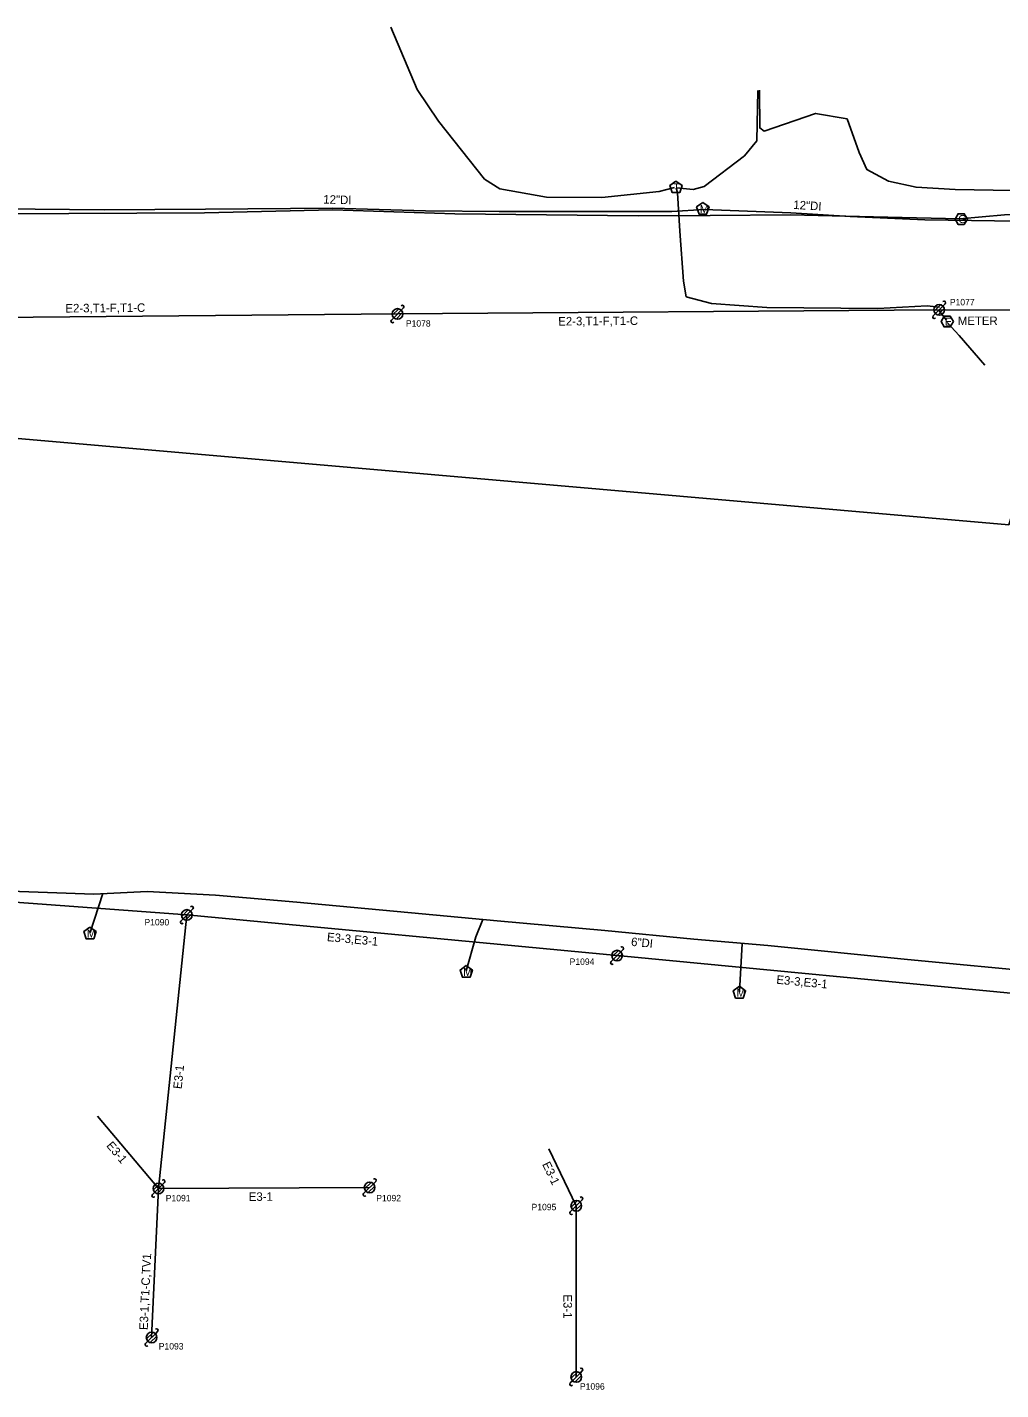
# Model space of a CAD drawing. Extents: x 1614474 to 1865144, y 1098877 to 1212550.
# Drawn here: x 1801312 to 1801769, y 1187738 to 1188377 of the extents above; entities that cross this region are included whole.
import ezdxf

# ---------------------------------------------------------------- set-up
doc = ezdxf.new("R2010")
doc.units = 0
for name, color, linetype in [('BFUSER_FIBERSPAN', 7, 'Continuous'), ('RD_EX_SU_Elec', 7, 'Continuous'), ('RD_EX_SU_Gas', 7, 'Continuous'), ('RD_EX_SU_H2O', 7, 'Continuous'), ('RD_EX_SU_Ovhd', 7, 'Continuous'), ('RD_EX_SU_Pole', 7, 'Continuous'), ('RD_EX_SU_Telecom', 7, 'Continuous'), ('RD_EX_SU_TX_Elec', 7, 'Continuous'), ('RD_EX_SU_TX_H2O', 7, 'Continuous'), ('RD_EX_SU_TX_Pole', 7, 'Continuous')]:
    doc.layers.add(name, color=color, linetype=linetype)

# ---------------------------------------------------------------- blocks, each defined once
blk = doc.blocks.new('SUE_GVC')
at = {"layer": 'RD_EX_SU_Gas'}
blk.add_lwpolyline([(1.44, -2.5), (2.89, 0), (1.44, 2.5), (-1.44, 2.5), (-2.89, 0), (-1.44, -2.5)], close=True, dxfattribs=at)
blk.add_text('G', height=3.75, dxfattribs=at).set_placement((-1.34, -1.88))
blk = doc.blocks.new('SUE_TPP')
at = {"layer": 'RD_EX_SU_Telecom'}
blk.add_lwpolyline([(0, 3), (-2.85, 0.93), (-1.76, -2.43), (1.76, -2.43), (2.85, 0.93)], close=True, dxfattribs=at)
blk.add_text('T', height=3.75, dxfattribs=at).set_placement((-1.25, -1.88))
blk = doc.blocks.new('SUE_WM')
at = {"layer": 'RD_EX_SU_H2O'}
blk.add_lwpolyline([(0, 3.05), (-2.9, 0.94), (-1.79, -2.47), (1.79, -2.47), (2.9, 0.94)], close=True, dxfattribs=at)
blk.add_text('M', height=3.75, dxfattribs=at).set_placement((-1.43, -1.88))
blk = doc.blocks.new('SUE_PP')
at = {"layer": 'RD_EX_SU_Pole'}
for p, q in [((-2.41, -0.65), (0.65, 2.41)), ((-1.77, -1.77), (1.77, 1.77)), ((-0.65, -2.41), (2.41, 0.65)), ((1.77, 1.77), (2.83, 2.83)), ((-2.83, -2.83), (-1.77, -1.77))]:
    blk.add_line(p, q, dxfattribs=at)
blk.add_circle((0, 0), 2.5, dxfattribs=at)
for centre, start, end in [((2.3, 3.36), 315, 135), ((-2.3, -3.36), 135, 315)]:
    blk.add_arc(centre, 0.75, start, end, dxfattribs=at)

msp = doc.modelspace()

# ---------------------------------------------------------------- linework, layer by layer
at = {"layer": 'BFUSER_FIBERSPAN'}
msp.add_lwpolyline([(1800084.25, 1188303.4), (1800779.19, 1188255.87), (1800833.78, 1188281.15), (1801076.57, 1188204.5), (1801772.73, 1188143.98), (1801793.73, 1188209.4), (1801787.99, 1188210.07)], dxfattribs=at)
at = {"layer": 'RD_EX_SU_Elec'}
msp.add_line((1801740.16, 1188244.25), (1801743.54, 1188239.79), dxfattribs=at)
msp.add_lwpolyline([(1801746.74, 1188239.17), (1801745.3, 1188241.67), (1801742.41, 1188241.67), (1801740.97, 1188239.17), (1801742.41, 1188236.67), (1801745.3, 1188236.67)], close=True, dxfattribs=at)
msp.add_lwpolyline([(1801743.9, 1188238.76), (1801749.5, 1188232.67), (1801761.56, 1188218.75)], dxfattribs=at)
at = {"layer": 'RD_EX_SU_Gas'}
msp.add_lwpolyline([(1801300.18, 1188289.75), (1801395.65, 1188290.16), (1801455.8, 1188291.53), (1801513.04, 1188289.66), (1801598.92, 1188288.81), (1801632.69, 1188288.87), (1801670.37, 1188289.16), (1801709.24, 1188288.32), (1801749.77, 1188287.36), (1801770.8, 1188289.23), (1801835.8, 1188289.57), (1801882.8, 1188288.37), (1801925.16, 1188284.33), (1801950.2, 1188282.64), (1801971.28, 1188282.21), (1801996.82, 1188281.83), (1802039.19, 1188282.29), (1802043.42, 1188284.85)], dxfattribs=at)
at = {"layer": 'RD_EX_SU_H2O'}
for p, q in [((1801341.96, 1187952.76), (1801347.89, 1187971.05)), ((1801646.47, 1187925.03), (1801647.68, 1187947.69))]:
    msp.add_line(p, q, dxfattribs=at)
for points in [[(1801299.98, 1188292.06), (1801348.52, 1188291.53), (1801396.06, 1188291.83), (1801455.82, 1188292.39), (1801499.16, 1188291.09), (1801533.71, 1188290.84), (1801614.7, 1188290.73), (1801629.95, 1188291.7), (1801670.47, 1188290.08), (1801698.41, 1188288.36), (1801733.35, 1188286.84), (1801787.88, 1188286.07), (1801857.46, 1188285.91)], [(1801295.73, 1187972.44), (1801343.67, 1187970.84), (1801368.71, 1187972.11), (1801400.74, 1187970.36), (1801438.8, 1187967.03), (1801497.7, 1187961.57), (1801532.75, 1187958.36), (1801583.27, 1187953.8), (1801624.99, 1187949.77), (1801659.67, 1187946.69), (1801725.3, 1187940.21), (1801791.08, 1187933.95)], [(1801518.36, 1187934.84), (1801522.8, 1187950.84), (1801526.05, 1187958.97)]]:
    msp.add_lwpolyline(points, dxfattribs=at)
at = {"layer": 'RD_EX_SU_Ovhd'}
for p, q in [((1801236.17, 1188240.62), (1801486.07, 1188242.75)), ((1801486.07, 1188242.75), (1801740.09, 1188244.68)), ((1801740.09, 1188244.68), (1801966.65, 1188244.29)), ((1801180.44, 1187976.55), (1801387.3, 1187961.03)), ((1801374.01, 1187832.8), (1801387.3, 1187961.03)), ((1801387.3, 1187961.03), (1801589.05, 1187942)), ((1801589.05, 1187942), (1801781.89, 1187923.55)), ((1801345.46, 1187866.75), (1801374.01, 1187832.8)), ((1801557, 1187851.42), (1801569.91, 1187824.74)), ((1801370.78, 1187762.99), (1801374.01, 1187832.8)), ((1801374.01, 1187832.8), (1801473.03, 1187833.3)), ((1801569.92, 1187744.5), (1801569.91, 1187824.74))]:
    msp.add_line(p, q, dxfattribs=at)
at = {"layer": 'RD_EX_SU_Pole'}
for p, q in [((1801737.67, 1188244.03), (1801740.73, 1188247.09)), ((1801738.32, 1188242.91), (1801741.85, 1188246.45)), ((1801741.85, 1188246.45), (1801742.92, 1188247.51)), ((1801483.24, 1188239.92), (1801484.3, 1188240.98)), ((1801483.66, 1188242.11), (1801486.72, 1188245.17)), ((1801484.3, 1188240.98), (1801487.84, 1188244.52)), ((1801485.42, 1188240.34), (1801488.49, 1188243.4)), ((1801487.84, 1188244.52), (1801488.9, 1188245.58)), ((1801737.26, 1188241.85), (1801738.32, 1188242.91)), ((1801739.44, 1188242.26), (1801742.5, 1188245.32)), ((1801384.47, 1187958.2), (1801385.53, 1187959.26)), ((1801384.89, 1187960.38), (1801387.95, 1187963.44)), ((1801385.53, 1187959.26), (1801389.07, 1187962.79)), ((1801386.66, 1187958.61), (1801389.72, 1187961.67)), ((1801389.07, 1187962.79), (1801390.13, 1187963.85)), ((1801586.23, 1187939.17), (1801587.29, 1187940.23)), ((1801586.64, 1187941.36), (1801589.7, 1187944.42)), ((1801587.29, 1187940.23), (1801590.82, 1187943.77)), ((1801588.41, 1187939.59), (1801591.47, 1187942.65)), ((1801590.82, 1187943.77), (1801591.88, 1187944.83)), ((1801371.59, 1187832.15), (1801374.65, 1187835.21)), ((1801372.24, 1187831.03), (1801375.77, 1187834.57)), ((1801373.36, 1187830.38), (1801376.42, 1187833.44)), ((1801375.77, 1187834.57), (1801376.83, 1187835.63)), ((1801470.2, 1187830.47), (1801471.26, 1187831.53)), ((1801470.61, 1187832.65), (1801473.67, 1187835.71)), ((1801471.26, 1187831.53), (1801474.8, 1187835.07)), ((1801472.38, 1187830.88), (1801475.44, 1187833.95)), ((1801474.8, 1187835.07), (1801475.86, 1187836.13)), ((1801371.18, 1187829.97), (1801372.24, 1187831.03)), ((1801567.5, 1187824.09), (1801570.56, 1187827.15)), ((1801568.14, 1187822.97), (1801571.68, 1187826.51)), ((1801569.26, 1187822.32), (1801572.33, 1187825.39)), ((1801571.68, 1187826.51), (1801572.74, 1187827.57)), ((1801567.08, 1187821.91), (1801568.14, 1187822.97))]:
    msp.add_line(p, q, dxfattribs=at)
for centre in [(1801740.09, 1188244.68), (1801486.07, 1188242.75), (1801387.3, 1187961.03), (1801589.05, 1187942), (1801374.01, 1187832.8), (1801473.03, 1187833.3), (1801569.91, 1187824.74)]:
    msp.add_circle(centre, 2.5, dxfattribs=at)
for centre, start, end in [((1801488.37, 1188246.11), 315, 135), ((1801742.38, 1188248.04), 315, 135), ((1801483.77, 1188239.39), 135, 315), ((1801737.79, 1188241.32), 135, 315), ((1801389.6, 1187964.38), 315, 135), ((1801385, 1187957.67), 135, 315), ((1801591.35, 1187945.36), 315, 135), ((1801586.76, 1187938.64), 135, 315), ((1801376.3, 1187836.16), 315, 135), ((1801475.33, 1187836.66), 315, 135), ((1801371.71, 1187829.44), 135, 315), ((1801470.73, 1187829.94), 135, 315), ((1801572.21, 1187828.1), 315, 135), ((1801567.61, 1187821.38), 135, 315)]:
    msp.add_arc(centre, 0.75, start, end, dxfattribs=at)
at = {"layer": 'RD_EX_SU_Telecom'}
for points in [[(1801483.02, 1188377.14), (1801495.27, 1188347.91), (1801505.36, 1188333.14), (1801526.9, 1188306), (1801534.1, 1188301.47), (1801555.99, 1188297.54), (1801581.95, 1188297.37), (1801608.8, 1188300.18), (1801615.95, 1188301.97)], [(1801616.99, 1188301.89), (1801624.74, 1188301.12), (1801629.93, 1188302.57), (1801648.75, 1188316.9), (1801654.6, 1188323.92), (1801655.04, 1188347.43)], [(1801655.86, 1188347.6), (1801655.95, 1188329.98), (1801657.97, 1188328.39), (1801682.15, 1188336.73), (1801696.88, 1188334.16), (1801702.52, 1188318.42), (1801706.09, 1188310.43), (1801716.39, 1188304.98), (1801729.28, 1188302.18), (1801747.59, 1188301.03), (1801801.04, 1188300.2), (1801837.59, 1188298.33), (1801845.25, 1188301.81), (1801856.3, 1188310.58), (1801861.71, 1188317.02)], [(1801616.73, 1188301.8), (1801617.37, 1188299.47), (1801618.54, 1188281.6), (1801620.13, 1188258.18), (1801621.47, 1188250.83), (1801633.25, 1188247.66), (1801659.31, 1188245.76), (1801711.36, 1188245.3), (1801734.42, 1188246.64), (1801740.17, 1188245.86)]]:
    msp.add_lwpolyline(points, dxfattribs=at)

# ---------------------------------------------------------------- block references
at = {"layer": 'RD_EX_SU_Gas'}
msp.add_blockref('SUE_GVC', (1801750.41, 1188287.24), dxfattribs=at)
at = {"layer": 'RD_EX_SU_H2O'}
for p in [(1801629.26, 1188291.95), (1801341.85, 1187952.35), (1801518.34, 1187934.28), (1801646.44, 1187924.56)]:
    msp.add_blockref('SUE_WM', p, dxfattribs=at)
at = {"layer": 'RD_EX_SU_Pole'}
for p in [(1801370.78, 1187762.99), (1801569.92, 1187744.5)]:
    msp.add_blockref('SUE_PP', p, dxfattribs=at)
at = {"layer": 'RD_EX_SU_Telecom'}
msp.add_blockref('SUE_TPP', (1801616.66, 1188302.07), dxfattribs=at)

# ---------------------------------------------------------------- texts
at = {"layer": 'RD_EX_SU_Elec'}
msp.add_text('E', height=3.75, dxfattribs=at).set_placement((1801742.69, 1188237.29))
at = {"layer": 'RD_EX_SU_Ovhd'}
for s, rotation, p in [('E2-3,T1-F,T1-C', 0.48976, (1801330.37, 1188243.42)), ('E2-3,T1-F,T1-C', 0.43437, (1801561.47, 1188237.32)), ('E3-3,E3-1', 354.61332, (1801452.87, 1187948.82)), ('E3-3,E3-1', 354.53372, (1801663.61, 1187928.84)), ('E3-1', 84.07984, (1801384.86, 1187879.31)), ('E3-1', 310.05197, (1801349.34, 1187852.81)), ('E3-1', 295.83111, (1801553.82, 1187844.21)), ('E3-1', 0.29001, (1801416.35, 1187827.01)), ('E3-1,T1-C,TV1', 87.35329, (1801368.94, 1187766.42)), ('E3-1', 270.00373, (1801563.91, 1187783.19))]:
    msp.add_text(s, height=4, rotation=rotation, dxfattribs=at).set_placement(p)
at = {"layer": 'RD_EX_SU_TX_Elec'}
msp.add_text('METER', height=4, dxfattribs=at).set_placement((1801748.82, 1188237.54))
at = {"layer": 'RD_EX_SU_TX_H2O'}
for s, rotation, p in [('12"DI', 358.28389, (1801451.23, 1188294.53)), ('12"DI', 356.48262, (1801671.61, 1188292.01)), ('6"DI', 354.47497, (1801595.48, 1187946.59))]:
    msp.add_text(s, height=4, rotation=rotation, dxfattribs=at).set_placement(p)
at = {"layer": 'RD_EX_SU_TX_Pole'}
for s, p in [('P1077', (1801745.11, 1188246.81)), ('P1078', (1801490.02, 1188236.82)), ('P1090', (1801367.43, 1187956.14)), ('P1094', (1801566.81, 1187937.66)), ('P1091', (1801377.42, 1187826.83)), ('P1092', (1801476.14, 1187826.83)), ('P1095', (1801548.95, 1187822.65)), ('P1093', (1801374.14, 1187757.36)), ('P1096', (1801571.64, 1187738.54))]:
    msp.add_text(s, height=3, dxfattribs=at).set_placement(p)

doc.saveas('drawing.dxf')
